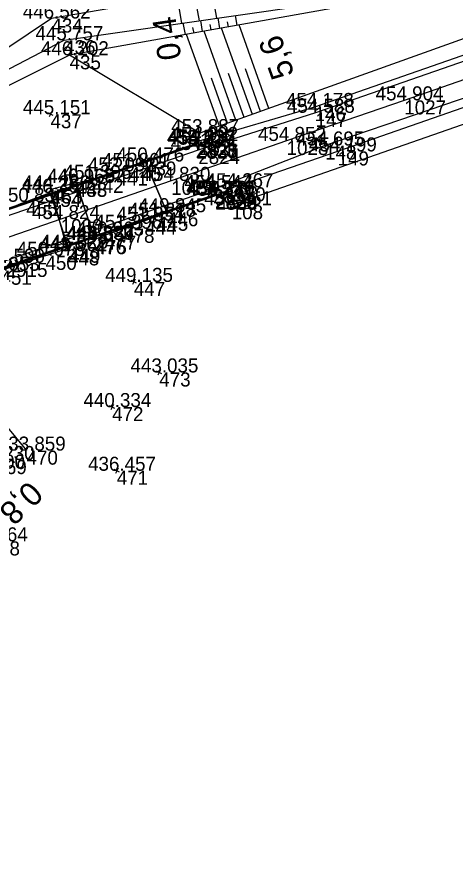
# Model space of a CAD drawing. Extents: x -751615 to -750797, y -1114905 to -1114561.
# Drawn here: x -751063 to -751025.5, y -1114713 to -1114641.5 of the extents above; entities that cross this region are included whole.
import ezdxf

# ---------------------------------------------------------------- set-up
doc = ezdxf.new("R2010")
doc.units = 0
for name, color, linetype in [('Vrstva 1', 7, 'Continuous'), ('Vrstva 17', 7, 'Continuous'), ('Vrstva 18', 7, 'Continuous'), ('Vrstva 4', 7, 'Continuous'), ('Vrstva 48', 7, 'Continuous'), ('Vrstva 49', 7, 'Continuous'), ('Vrstva 60', 7, 'Continuous'), ('Vrstva 61', 7, 'Continuous')]:
    doc.layers.add(name, color=color, linetype=linetype)

msp = doc.modelspace()

# ---------------------------------------------------------------- linework, layer by layer
at = {"layer": 'Vrstva 1'}
for points in [[(-751020.123, -1114645.246), (-751029.869, -1114648.612), (-751039.93, -1114652.08), (-751049.798, -1114655.49)], [(-751049.798, -1114655.49), (-751059.246, -1114658.755), (-751068.733, -1114662.026), (-751078.259, -1114665.311), (-751087.386, -1114668.46), (-751094.716, -1114670.988), (-751098.18, -1114672.185), (-751107.899, -1114675.542), (-751117.566, -1114678.875), (-751127.151, -1114682.181), (-751136.66, -1114685.456), (-751145.831, -1114688.627), (-751153.169, -1114691.158), (-751162.606, -1114694.412), (-751172.056, -1114697.672), (-751181.572, -1114700.954), (-751190.356, -1114703.987), (-751200.827, -1114707.603), (-751207.289, -1114709.832), (-751216.509, -1114713.014)]]:
    msp.add_lwpolyline(points, dxfattribs=at)
at = {"layer": 'Vrstva 17'}
for points in [[(-751047.703, -1114652.345), (-751074.623, -1114661.619), (-751099.27, -1114670.16)], [(-751046.01, -1114656.691), (-751073.182, -1114666.054), (-751097.643, -1114674.51)]]:
    msp.add_lwpolyline(points, dxfattribs=at)
at = {"layer": 'Vrstva 18'}
for p, q in [((-751047.645, -1114652.397), (-751052.033, -1114653.832)), ((-751050.159, -1114658.166), (-751052.033, -1114653.832)), ((-751056.269, -1114660.55), (-751057.949, -1114655.656)), ((-751057.937, -1114655.641), (-751056.338, -1114660.529)), ((-751060.164, -1114656.515), (-751058.538, -1114661.28)), ((-751058.625, -1114661.506), (-751060.073, -1114656.219))]:
    msp.add_line(p, q, dxfattribs=at)
for points in [[(-751047.676, -1114652.299), (-751074.414, -1114661.508), (-751099.176, -1114670.054)], [(-751047.676, -1114652.3), (-751074.421, -1114661.513), (-751099.17, -1114670.052)], [(-751047.485, -1114652.852), (-751047.676, -1114652.3), (-751047.676, -1114652.299), (-751047.645, -1114652.397), (-751047.485, -1114652.852)], [(-751047.485, -1114652.852), (-751074.245, -1114662.097), (-751099.037, -1114670.633), (-751120.593, -1114678.106), (-751141.938, -1114685.464), (-751163.608, -1114692.915), (-751187.181, -1114701.023)], [(-751047.645, -1114652.397), (-751074.404, -1114661.645), (-751099.13, -1114670.169)], [(-751057.937, -1114655.641), (-751057.949, -1114655.656), (-751060.073, -1114656.219), (-751060.164, -1114656.515)], [(-751046.217, -1114656.195), (-751073.081, -1114665.441), (-751097.909, -1114674.024), (-751119.627, -1114681.519), (-751140.891, -1114688.815), (-751162.437, -1114696.278), (-751186.019, -1114704.426)], [(-751046.217, -1114656.195), (-751046.015, -1114656.761), (-751046.019, -1114656.761), (-751046.052, -1114656.653), (-751046.217, -1114656.195)], [(-751046.052, -1114656.653), (-751072.928, -1114665.893), (-751097.576, -1114674.43)], [(-751046.019, -1114656.761), (-751072.884, -1114665.984), (-751097.551, -1114674.5)], [(-751046.015, -1114656.761), (-751072.885, -1114665.984), (-751097.549, -1114674.502)], [(-751051.016, -1114658.552), (-751050.159, -1114658.166), (-751046.052, -1114656.653)], [(-751058.538, -1114661.28), (-751058.625, -1114661.506), (-751056.269, -1114660.55), (-751056.338, -1114660.529)]]:
    msp.add_lwpolyline(points, dxfattribs=at)
for centre, major_axis, ratio, start_param, end_param in [((-751054.425, -1114654.625), (2.625, 0.89), 0.014546, 4.689397, 5.853432), ((-751054.564, -1114654.516), (3.446, 1.111), 0.05193, 3.331587, 4.722243), ((-751065.634, -1114658.626), (5.471, 2.11), 0.004805, 0.014809, 1.725149), ((-751052.98, -1114659.392), (-3.204, -1.169), 0.04356, 4.036567, 4.990518), ((-751053.191, -1114659.416), (-3.151, -1.12), 0.026639, 4.932885, 6.222614), ((-751064.131, -1114663.174), (-5.615, -1.893), 0.015587, 3.224762, 4.754054)]:
    msp.add_ellipse(centre, major_axis=major_axis, ratio=ratio, start_param=start_param, end_param=end_param, dxfattribs=at)
at = {"layer": 'Vrstva 4'}
for p, q in [((-751037.448, -1114649.672), (-751047.485, -1114652.852)), ((-751047.428, -1114652.085), (-751047.645, -1114652.397)), ((-751047.645, -1114652.397), (-751047.485, -1114652.852)), ((-751036.639, -1114652.467), (-751046.217, -1114656.195)), ((-751044.403, -1114656.035), (-751045.759, -1114656.694))]:
    msp.add_line(p, q, dxfattribs=at)
for points in [[(-750909.854, -1114605.662), (-750913.632, -1114606.277), (-750928.936, -1114611.392), (-750945.448, -1114617.255), (-750962.947, -1114623.179), (-750985.088, -1114630.83), (-751003.049, -1114637.15), (-751019.956, -1114643.079), (-751037.537, -1114649.178), (-751047.428, -1114652.085)], [(-750909.854, -1114605.662), (-750913.482, -1114606.81), (-750928.752, -1114612.038), (-750945.395, -1114617.786), (-750962.769, -1114623.789), (-750984.849, -1114631.395), (-751002.837, -1114637.648), (-751019.817, -1114643.56), (-751037.448, -1114649.672)], [(-750908.397, -1114608.245), (-750913.156, -1114610.918), (-750927.279, -1114615.559), (-750944.077, -1114621.468), (-750961.07, -1114627.222), (-750983.47, -1114634.851), (-751001.346, -1114641.244), (-751018.647, -1114647.092), (-751035.567, -1114652.973), (-751044.403, -1114656.035)], [(-750908.397, -1114608.245), (-750913.028, -1114609.922), (-750927.564, -1114615.039), (-750944.227, -1114620.718), (-750961.521, -1114626.651), (-750983.784, -1114634.327), (-751001.734, -1114640.382), (-751018.892, -1114646.443), (-751036.639, -1114652.467)], [(-751047.485, -1114652.852), (-751074.245, -1114662.097), (-751099.037, -1114670.633), (-751120.593, -1114678.106), (-751141.938, -1114685.464), (-751163.608, -1114692.915), (-751187.181, -1114701.023)], [(-751046.217, -1114656.195), (-751073.081, -1114665.441), (-751097.909, -1114674.024), (-751119.627, -1114681.519), (-751140.891, -1114688.815), (-751162.437, -1114696.278), (-751186.019, -1114704.426)], [(-751045.759, -1114656.694), (-751046.052, -1114656.653), (-751046.217, -1114656.195)]]:
    msp.add_lwpolyline(points, dxfattribs=at)
at = {"layer": 'Vrstva 48'}
for p, q in [((-751046.335, -1114639.267), (-751045.936, -1114641.594)), ((-751049.292, -1114639.775), (-751048.906, -1114642.022)), ((-751047.814, -1114639.521), (-751047.421, -1114641.808)), ((-751045.634, -1114642.462), (-751045.793, -1114641.573)), ((-751044.158, -1114642.198), (-751044.308, -1114641.359)), ((-751048.587, -1114642.99), (-751048.764, -1114642.001)), ((-751047.111, -1114642.726), (-751047.279, -1114641.787)), ((-751046.373, -1114642.594), (-751046.454, -1114642.137)), ((-751044.896, -1114642.33), (-751044.973, -1114641.898)), ((-751041.444, -1114649.303), (-751043.996, -1114642.17)), ((-751045.681, -1114650.819), (-751048.488, -1114642.972)), ((-751047.849, -1114642.858), (-751047.935, -1114642.376)), ((-751044.269, -1114650.314), (-751046.991, -1114642.705)), ((-751042.857, -1114649.809), (-751045.494, -1114642.437)), ((-751043.563, -1114650.061), (-751044.903, -1114646.316)), ((-751042.15, -1114649.556), (-751043.448, -1114645.93)), ((-751044.975, -1114650.567), (-751046.357, -1114646.702))]:
    msp.add_line(p, q, dxfattribs=at)
at = {"layer": 'Vrstva 49'}
for p, q in [((-751058.95, -1114643.469), (-751019.246, -1114637.748)), ((-751047.344, -1114651.414), (-751058.49, -1114644.759)), ((-751059.898, -1114649.902), (-751060.348, -1114649.684)), ((-751060.014, -1114649.568), (-751060.232, -1114650.018)), ((-751052.769, -1114664.231), (-751053.219, -1114664.013)), ((-751052.885, -1114663.897), (-751053.103, -1114664.347)), ((-751050.71, -1114671.631), (-751050.928, -1114672.081)), ((-751050.594, -1114671.965), (-751051.044, -1114671.747)), ((-751054.627, -1114674.923), (-751055.077, -1114674.705)), ((-751054.743, -1114674.589), (-751054.961, -1114675.039)), ((-751054.228, -1114680.364), (-751054.678, -1114680.146)), ((-751054.344, -1114680.03), (-751054.562, -1114680.48))]:
    msp.add_line(p, q, dxfattribs=at)
for points in [[(-750970.963, -1114625.07), (-750996.446, -1114634.135), (-751018.226, -1114640.997), (-751047.344, -1114651.414), (-751047.645, -1114652.397)], [(-751020.117, -1114634.765), (-751060.04, -1114641.62), (-751070.127, -1114648.352), (-751076.528, -1114658.314), (-751078.11, -1114663.715)], [(-751019.246, -1114637.748), (-751058.49, -1114644.759), (-751068.921, -1114649.956), (-751075.459, -1114658.878), (-751078.11, -1114663.715)], [(-751078.11, -1114663.715), (-751075.662, -1114658.603), (-751069.572, -1114648.996), (-751058.95, -1114643.469)], [(-751016.335, -1114647.709), (-751044.621, -1114657.572), (-751046.052, -1114656.653)], [(-751047.645, -1114652.397), (-751052.033, -1114653.832), (-751050.159, -1114658.166), (-751046.052, -1114656.653)], [(-751078.11, -1114663.715), (-751072.259, -1114666.654), (-751067.724, -1114671.829), (-751062.168, -1114678.533)]]:
    msp.add_lwpolyline(points, dxfattribs=at)
at = {"layer": 'Vrstva 60'}
for p, q in [((-751060.04, -1114641.62), (-751060.04, -1114641.62)), ((-751058.95, -1114643.469), (-751058.95, -1114643.469)), ((-751058.49, -1114644.759), (-751058.49, -1114644.759)), ((-751029.869, -1114648.612), (-751029.869, -1114648.612)), ((-751037.537, -1114649.178), (-751037.537, -1114649.178)), ((-751060.123, -1114649.793), (-751060.123, -1114649.793)), ((-751037.448, -1114649.672), (-751037.448, -1114649.672)), ((-751047.344, -1114651.414), (-751047.344, -1114651.414)), ((-751047.676, -1114652.299), (-751047.676, -1114652.299)), ((-751047.676, -1114652.3), (-751047.676, -1114652.3)), ((-751047.428, -1114652.085), (-751047.428, -1114652.085)), ((-751039.93, -1114652.08), (-751039.93, -1114652.08)), ((-751047.703, -1114652.345), (-751047.703, -1114652.345)), ((-751047.645, -1114652.397), (-751047.645, -1114652.397)), ((-751047.485, -1114652.852), (-751047.485, -1114652.852)), ((-751036.639, -1114652.467), (-751036.639, -1114652.467)), ((-751035.567, -1114652.973), (-751035.567, -1114652.973)), ((-751053.362, -1114654.304), (-751053.362, -1114654.304)), ((-751052.033, -1114653.832), (-751052.033, -1114653.832)), ((-751054.472, -1114654.684), (-751054.472, -1114654.684)), ((-751057.949, -1114655.656), (-751057.949, -1114655.656)), ((-751057.937, -1114655.641), (-751057.937, -1114655.641)), ((-751056.55, -1114655.316), (-751056.55, -1114655.316)), ((-751049.798, -1114655.49), (-751049.798, -1114655.49)), ((-751060.164, -1114656.515), (-751060.164, -1114656.515)), ((-751060.073, -1114656.219), (-751060.073, -1114656.219)), ((-751046.217, -1114656.195), (-751046.217, -1114656.195)), ((-751044.403, -1114656.035), (-751044.403, -1114656.035)), ((-751062.199, -1114657.277), (-751062.199, -1114657.277)), ((-751046.052, -1114656.653), (-751046.052, -1114656.653)), ((-751046.019, -1114656.761), (-751046.019, -1114656.761)), ((-751046.015, -1114656.761), (-751046.015, -1114656.761)), ((-751046.01, -1114656.691), (-751046.01, -1114656.691)), ((-751045.759, -1114656.694), (-751045.759, -1114656.694)), ((-751044.621, -1114657.572), (-751044.621, -1114657.572)), ((-751059.246, -1114658.755), (-751059.246, -1114658.755)), ((-751051.016, -1114658.552), (-751051.016, -1114658.552)), ((-751050.159, -1114658.166), (-751050.159, -1114658.166)), ((-751052.021, -1114658.892), (-751052.021, -1114658.892)), ((-751055.472, -1114660.161), (-751055.472, -1114660.161)), ((-751053.909, -1114659.579), (-751053.909, -1114659.579)), ((-751056.338, -1114660.529), (-751056.338, -1114660.529)), ((-751056.269, -1114660.55), (-751056.269, -1114660.55)), ((-751058.625, -1114661.506), (-751058.625, -1114661.506)), ((-751058.538, -1114661.28), (-751058.538, -1114661.28)), ((-751060.551, -1114661.892), (-751060.551, -1114661.892)), ((-751052.994, -1114664.122), (-751052.994, -1114664.122)), ((-751050.819, -1114671.856), (-751050.819, -1114671.856)), ((-751054.852, -1114674.814), (-751054.852, -1114674.814)), ((-751062.168, -1114678.533), (-751062.168, -1114678.533)), ((-751054.453, -1114680.255), (-751054.453, -1114680.255))]:
    msp.add_line(p, q, dxfattribs=at)

# ---------------------------------------------------------------- texts
at = {"layer": 'Vrstva 48'}
for s, rotation, p in [('0,4', 98.19939, (-751048.923, -1114645.027)), ('5,6', 109.68473, (-751039.239, -1114646.369)), ('0,8', 224.29611, (-751061.983, -1114681.013))]:
    msp.add_text(s, height=2, rotation=rotation, dxfattribs=at).set_placement(p)
at = {"layer": 'Vrstva 60'}
for s, p in [('434', (-751060.04, -1114642.82)), ('436', (-751058.95, -1114644.669)), ('435', (-751058.49, -1114645.959)), ('1027', (-751029.869, -1114649.812)), ('146', (-751037.537, -1114650.378)), ('437', (-751060.123, -1114650.993)), ('147', (-751037.448, -1114650.872)), ('106', (-751047.344, -1114652.614)), ('2833', (-751047.703, -1114653.545)), ('2826', (-751047.676, -1114653.499)), ('2825', (-751047.676, -1114653.5)), ('152', (-751047.428, -1114653.285)), ('1028', (-751039.93, -1114653.28)), ('2827', (-751047.645, -1114653.597)), ('2824', (-751047.485, -1114654.052)), ('148', (-751036.639, -1114653.667)), ('149', (-751035.567, -1114654.173)), ('440', (-751053.362, -1114655.504)), ('439', (-751052.033, -1114655.032)), ('441', (-751054.472, -1114655.884)), ('438', (-751057.949, -1114656.856)), ('443', (-751057.937, -1114656.841)), ('442', (-751056.55, -1114656.516)), ('1029', (-751049.798, -1114656.69)), ('454', (-751060.164, -1114657.715)), ('453', (-751060.073, -1114657.419)), ('2831', (-751046.217, -1114657.395)), ('150', (-751044.403, -1114657.235)), ('455', (-751062.199, -1114658.477)), ('2828', (-751046.052, -1114657.853)), ('2829', (-751046.019, -1114657.961)), ('2830', (-751046.015, -1114657.961)), ('2832', (-751046.01, -1114657.891)), ('151', (-751045.759, -1114657.894)), ('108', (-751044.621, -1114658.772)), ('1030', (-751059.246, -1114659.955)), ('445', (-751051.016, -1114659.752)), ('446', (-751050.159, -1114659.366)), ('444', (-751052.021, -1114660.092)), ('477', (-751055.472, -1114661.361)), ('478', (-751053.909, -1114660.779)), ('476', (-751056.338, -1114661.729)), ('475', (-751056.269, -1114661.75)), ('448', (-751058.625, -1114662.706)), ('449', (-751058.538, -1114662.48)), ('450', (-751060.551, -1114663.092)), ('2915', (-751063.946, -1114663.692)), ('451', (-751064.394, -1114664.365)), ('447', (-751052.994, -1114665.322)), ('473', (-751050.819, -1114673.056)), ('472', (-751054.852, -1114676.014)), ('470', (-751062.168, -1114679.733)), ('469', (-751064.827, -1114680.538)), ('471', (-751054.453, -1114681.455)), ('378', (-751065.412, -1114687.486))]:
    msp.add_text(s, height=1.2, dxfattribs=at).set_placement(p)
at = {"layer": 'Vrstva 61'}
for s, p in [('446.562', (-751062.488, -1114641.62)), ('445.757', (-751061.402, -1114643.469)), ('446.202', (-751060.938, -1114644.759)), ('454.178', (-751039.991, -1114649.178)), ('454.904', (-751032.32, -1114648.612)), ('445.151', (-751062.48, -1114649.793)), ('454.588', (-751039.902, -1114649.672)), ('454.092', (-751049.876, -1114652.085)), ('453.887', (-751049.796, -1114651.414)), ('454.852', (-751042.378, -1114652.08)), ('455.726', (-751050.155, -1114652.345)), ('454.237', (-751050.128, -1114652.299)), ('454.537', (-751050.128, -1114652.3)), ('454.237', (-751050.097, -1114652.397)), ('454.695', (-751039.095, -1114652.467)), ('454.541', (-751049.842, -1114652.852)), ('454.199', (-751038.021, -1114652.973)), ('450.476', (-751054.485, -1114653.832)), ('452.092', (-751056.92, -1114654.684)), ('451.861', (-751055.719, -1114654.304)), ('446.968', (-751060.403, -1114655.656)), ('449.159', (-751060.391, -1114655.641)), ('451.396', (-751059.002, -1114655.316)), ('454.830', (-751052.249, -1114655.49)), ('444.286', (-751062.525, -1114656.219)), ('454.544', (-751048.668, -1114656.195)), ('454.267', (-751046.855, -1114656.035)), ('446.364', (-751062.615, -1114656.515)), ('454.236', (-751048.504, -1114656.653)), ('454.240', (-751048.47, -1114656.761)), ('454.540', (-751048.466, -1114656.761)), ('455.722', (-751048.458, -1114656.691)), ('454.136', (-751048.211, -1114656.694)), ('450.834', (-751064.65, -1114657.277)), ('453.751', (-751046.978, -1114657.572)), ('451.278', (-751053.47, -1114658.552)), ('449.845', (-751052.615, -1114658.166)), ('454.824', (-751061.697, -1114658.755)), ('451.854', (-751054.472, -1114658.892)), ('451.896', (-751056.361, -1114659.579)), ('448.836', (-751058.79, -1114660.529)), ('446.687', (-751058.721, -1114660.55)), ('450.963', (-751057.924, -1114660.161)), ('446.626', (-751060.99, -1114661.28)), ('450.678', (-751063.005, -1114661.892)), ('443.562', (-751061.073, -1114661.506)), ('454.590', (-751066.397, -1114662.492)), ('452.053', (-751066.846, -1114663.165)), ('449.135', (-751055.45, -1114664.122)), ('443.035', (-751053.275, -1114671.856)), ('440.334', (-751057.303, -1114674.814)), ('433.859', (-751064.622, -1114678.533)), ('433.230', (-751067.278, -1114679.338)), ('432.400', (-751068.104, -1114680.07)), ('436.457', (-751056.905, -1114680.255)), ('431.964', (-751067.863, -1114686.286))]:
    msp.add_text(s, height=1.2, dxfattribs=at).set_placement(p)

doc.saveas('drawing.dxf')
